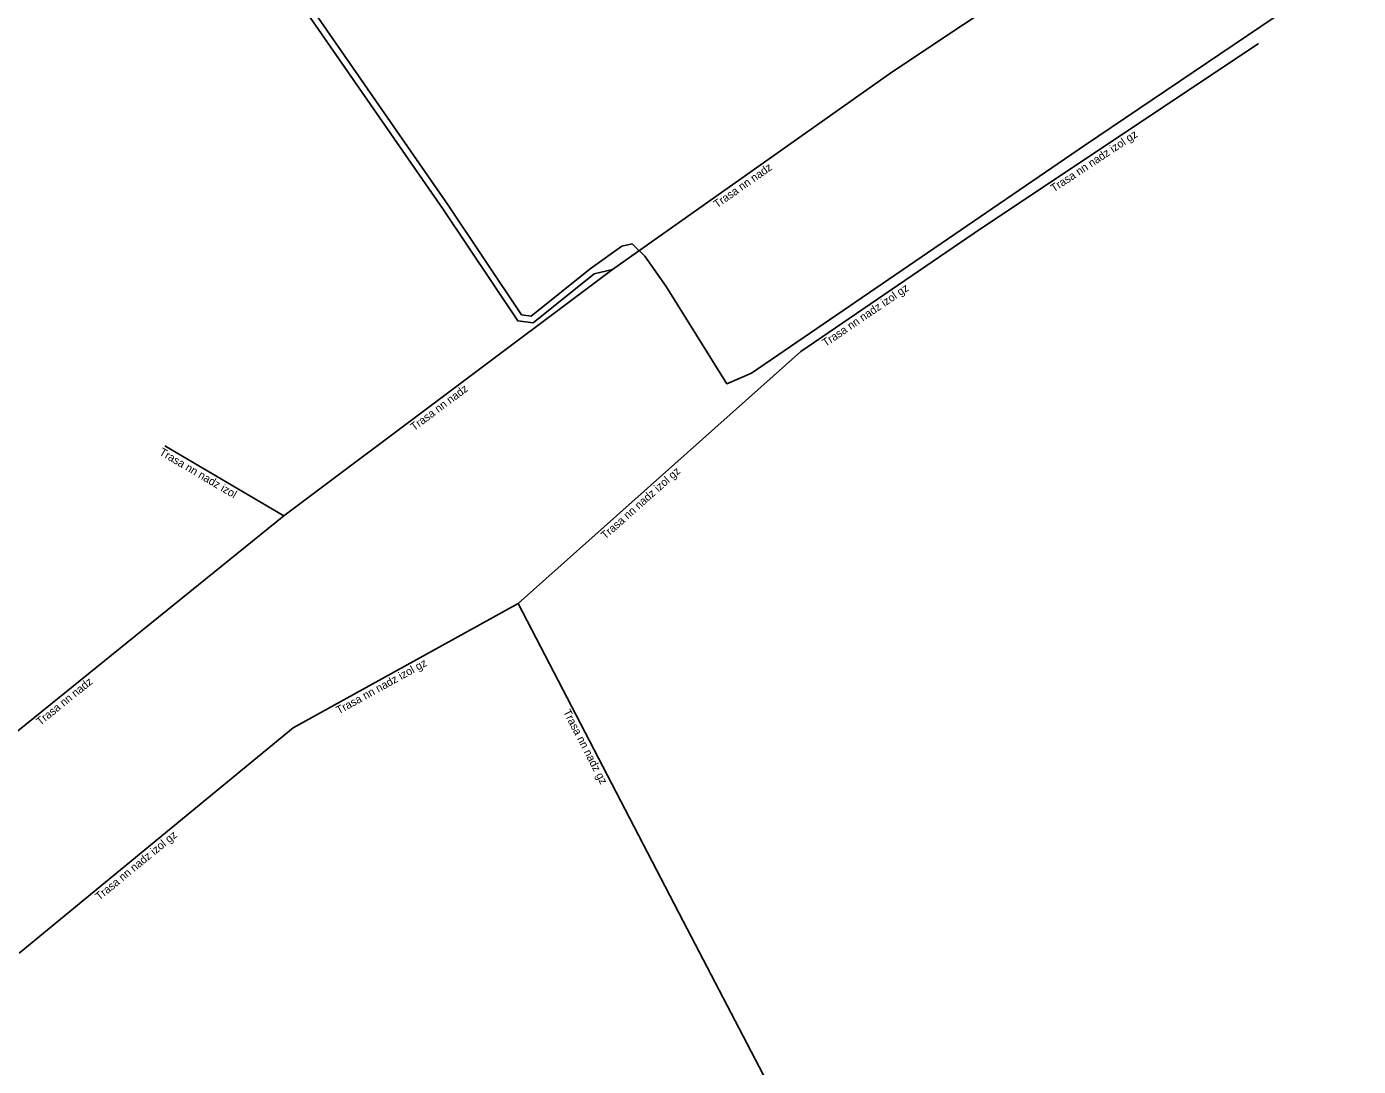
# Model space of a CAD drawing. Extents: x -468149 to -467677, y -1100197 to -1099840.
# Drawn here: x -468014.2 to -467931, y -1100071.5 to -1100006.5 of the extents above; entities that cross this region are included whole.
import ezdxf

# ---------------------------------------------------------------- set-up
doc = ezdxf.new("R2010")
doc.units = 0
for name, color, linetype in [('Popiskový text - Ostatní atributy Trasy', 7, 'Continuous'), ('Spojnice NN', 7, 'Continuous'), ('Spojnice VN', 7, 'Continuous')]:
    doc.layers.add(name, color=color, linetype=linetype)

msp = doc.modelspace()

# ---------------------------------------------------------------- linework, layer by layer
at = {"layer": 'Spojnice NN'}
for points in [[(-467977.61, -1100021.71), (-467978.753, -1100021.987), (-467982.581, -1100025.05), (-467983.538, -1100024.922), (-467988.219, -1100017.91), (-467998.856, -1100002.534), (-468008.207, -1099989.502), (-468009.795, -1099990.508), (-468010.862, -1099990.383), (-468012.131, -1099988.334), (-468013.77, -1099985.352), (-468011.734, -1099984.01), (-468009.576, -1099986.317)], [(-467933.282, -1099991.465), (-467960.151, -1100009.378)], [(-467955.006, -1100019.432), (-467937.234, -1100007.582)], [(-467960.151, -1100009.378), (-467977.61, -1100021.71)], [(-467965.837, -1100026.826), (-467955.006, -1100019.432)], [(-467977.61, -1100021.71), (-467998.156, -1100037.114)], [(-467983.5, -1100042.58), (-467965.837, -1100026.826)], [(-468005.586, -1100032.739), (-467998.156, -1100037.114)], [(-467998.156, -1100037.114), (-468024.514, -1100058.401)], [(-467997.576, -1100050.365), (-467983.5, -1100042.58)], [(-467973.2, -1100062.45), (-467983.5, -1100042.58)], [(-468014.686, -1100064.45), (-467997.576, -1100050.365)], [(-467973.2, -1100062.45), (-467959.67, -1100088.377)]]:
    msp.add_lwpolyline(points, dxfattribs=at)
at = {"layer": 'Spojnice VN'}
msp.add_lwpolyline([(-467929.47, -1100001.36), (-467948.11, -1100013.96), (-467968.93, -1100028.2), (-467970.46, -1100028.85), (-467974.27, -1100022.77), (-467975.59, -1100020.87), (-467976.39, -1100020.1), (-467977.04, -1100020.26), (-467979, -1100021.66), (-467982.7, -1100024.62), (-467983.3, -1100024.54), (-467987.88, -1100017.68), (-467998.52, -1100002.3), (-468007.98, -1099988.83), (-468008.73, -1099988.67), (-468009.58, -1099988.9), (-468010.24, -1099988.6), (-468010.56, -1099988.04), (-468011.88, -1099986.25), (-468011.89, -1099985.32), (-468011.14, -1099985.04), (-468010.7, -1099985.06), (-468010.11, -1099984.82), (-468009.576, -1099986.317)], dxfattribs=at)

# ---------------------------------------------------------------- texts
at = {"layer": 'Popiskový text - Ostatní atributy Trasy'}
for s, rotation, p in [('Trasa nn nadz izol gz', 33.69342, (-467950.032, -1100016.897)), ('Trasa nn nadz', 35.23511, (-467971.077, -1100017.891)), ('Trasa nn nadz izol gz', 34.31653, (-467964.297, -1100026.561)), ('Trasa nn nadz', 36.86008, (-467990.011, -1100031.82)), ('Trasa nn nadz izol', 329.51062, (-468005.984, -1100033.259)), ('Trasa nn nadz izol gz', 41.73215, (-467978.068, -1100038.606)), ('Trasa nn nadz izol gz', 28.94484, (-467994.717, -1100049.526)), ('Trasa nn nadz', 38.92471, (-468013.376, -1100050.241)), ('Trasa nn nadz gz', 297.40027, (-467980.719, -1100049.357)), ('Trasa nn nadz izol gz', 39.46049, (-468009.683, -1100061.173))]:
    msp.add_text(s, height=0.5, rotation=rotation, dxfattribs=at).set_placement(p)

doc.saveas('drawing.dxf')
